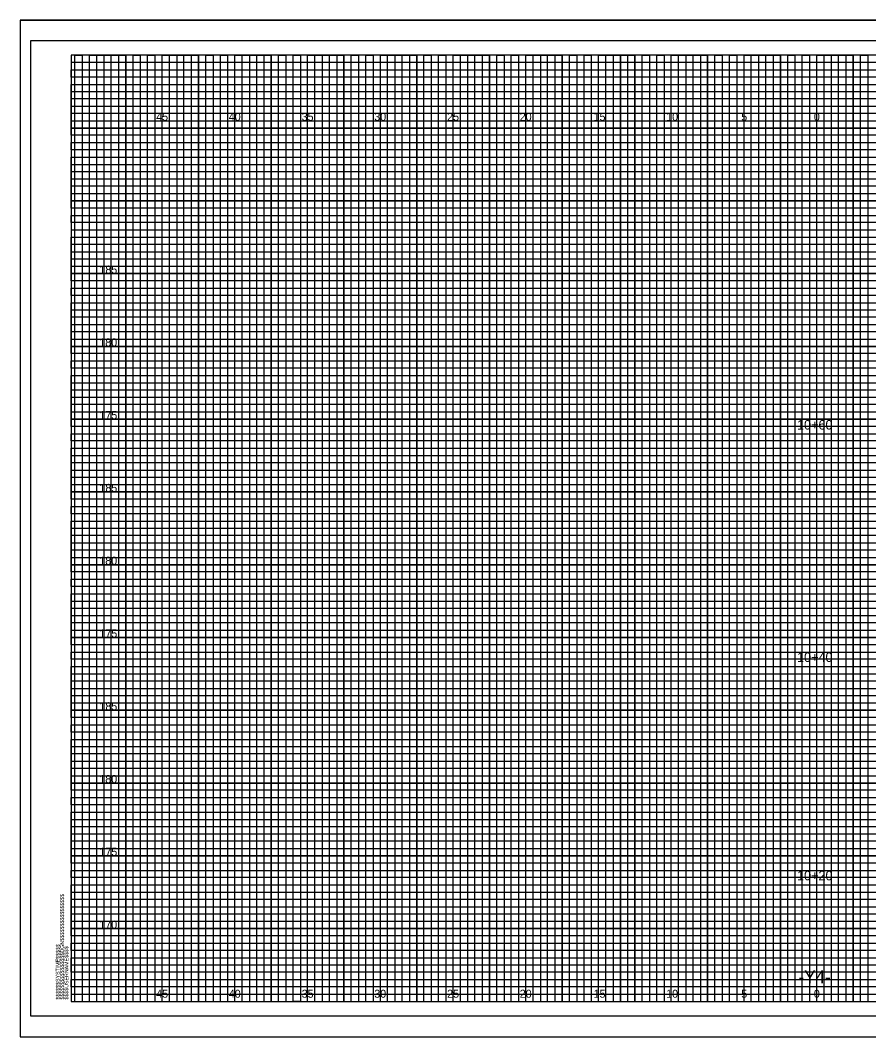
# Model space of a CAD drawing. Extents: x -4 to 103, y -2 to 138.
# Drawn here: x -3.5 to 54.8, y -2.4 to 67.4 of the extents above; entities that cross this region are included whole.
import ezdxf

# ---------------------------------------------------------------- set-up
doc = ezdxf.new("R2010")
doc.units = 0
for name, color, linetype in [('Old_Level_10', 7, 'Continuous'), ('Old_Level_3', 7, 'Continuous'), ('Old_Level_4', 7, 'Continuous'), ('Old_Level_5', 7, 'Continuous'), ('Old_Level_8', 7, 'Continuous'), ('Prop XS Dump Level', 7, 'Continuous'), ('Prop XS Elevation Labels', 7, 'Continuous'), ('Prop XS EOT Tick Mark', 7, 'Continuous'), ('Prop XS Finish Grade', 7, 'Continuous'), ('Prop XS Finish Grade Pavement', 7, 'Continuous'), ('Prop XS Subgrade Concrete', 7, 'Continuous')]:
    doc.layers.add(name, color=color, linetype=linetype)

msp = doc.modelspace()

# ---------------------------------------------------------------- linework, layer by layer
at = {"layer": 'Old_Level_10'}
for p, q in [((1.25, 0), (1.25, 65)), ((3.75, 0), (3.75, 65)), ((6.25, 0), (6.25, 65)), ((8.75, 0), (8.75, 65)), ((11.25, 0), (11.25, 65)), ((13.75, 0), (13.75, 65)), ((16.25, 0), (16.25, 65)), ((18.75, 0), (18.75, 65)), ((21.25, 0), (21.25, 65)), ((23.75, 0), (23.75, 65)), ((26.25, 0), (26.25, 65)), ((28.75, 0), (28.75, 65)), ((31.25, 0), (31.25, 65)), ((33.75, 0), (33.75, 65)), ((36.25, 0), (36.25, 65)), ((38.75, 0), (38.75, 65)), ((41.25, 0), (41.25, 65)), ((43.75, 0), (43.75, 65)), ((46.25, 0), (46.25, 65)), ((48.75, 0), (48.75, 65)), ((51.25, 0), (51.25, 65)), ((53.75, 0), (53.75, 65)), ((0, 62.5), (74.25, 62.5)), ((0, 60), (102.5, 60)), ((0, 57.5), (102.5, 57.5)), ((0, 55), (102.5, 55)), ((0, 52.5), (102.5, 52.5)), ((0, 50), (102.5, 50)), ((0, 47.5), (102.5, 47.5)), ((0, 45), (102.5, 45)), ((0, 42.5), (102.5, 42.5)), ((0, 40), (102.5, 40)), ((0, 37.5), (102.5, 37.5)), ((0, 35), (102.5, 35)), ((0, 32.5), (102.5, 32.5)), ((0, 30), (102.5, 30)), ((0, 27.5), (102.5, 27.5)), ((0, 25), (102.5, 25)), ((0, 22.5), (102.5, 22.5)), ((0, 20), (102.5, 20)), ((0, 17.5), (102.5, 17.5)), ((0, 15), (102.5, 15)), ((0, 12.5), (102.5, 12.5)), ((0, 10), (102.5, 10)), ((0, 7.5), (102.5, 7.5)), ((0, 5), (102.5, 5)), ((0, 2.5), (102.5, 2.5))]:
    msp.add_line(p, q, dxfattribs=at)
at = {"layer": 'Old_Level_3'}
for p, q in [((-3.5, 67.4), (103.4, 67.4)), ((-3.5, 67.4), (-3.5, -2.425)), ((-3.5, -2.425), (103.4, -2.425))]:
    msp.add_line(p, q, dxfattribs=at)
at = {"layer": 'Old_Level_4'}
msp.add_lwpolyline([(103, 66), (-2.8, 66), (-2.8, -1), (103, -1)], close=True, dxfattribs=at)
at = {"layer": 'Old_Level_5'}
msp.add_lwpolyline([(103.4, 67.4), (-3.5, 67.4), (-3.5, -2.425), (103.4, -2.425)], close=True, dxfattribs=at)
at = {"layer": 'Old_Level_8'}
for points in [[(1.25, 0), (1.25, 65), (3.75, 65), (3.75, 0), (6.25, 0), (6.25, 65), (8.75, 65), (8.75, 0), (11.25, 0), (11.25, 65), (13.75, 65), (13.75, 0), (16.25, 0), (16.25, 65), (18.75, 65), (18.75, 0), (21.25, 0), (21.25, 65), (23.75, 65), (23.75, 0), (26.25, 0), (26.25, 65), (28.75, 65), (28.75, 0), (31.25, 0), (31.25, 65), (33.75, 65), (33.75, 0), (36.25, 0), (36.25, 65), (38.75, 65), (38.75, 0), (41.25, 0), (41.25, 65), (43.75, 65), (43.75, 0), (46.25, 0), (46.25, 65), (48.75, 65), (48.75, 0), (51.25, 0), (51.25, 65), (53.75, 65), (53.75, 0)], [(102.5, 60), (0, 60), (0, 62.5), (74.25, 62.5)], [(102.5, 55), (0, 55), (0, 57.5), (102.5, 57.5)], [(102.5, 50), (0, 50), (0, 52.5), (102.5, 52.5)], [(102.5, 45), (0, 45), (0, 47.5), (102.5, 47.5)], [(102.5, 40), (0, 40), (0, 42.5), (102.5, 42.5)], [(102.5, 35), (0, 35), (0, 37.5), (102.5, 37.5)], [(102.5, 30), (0, 30), (0, 32.5), (102.5, 32.5)], [(102.5, 25), (0, 25), (0, 27.5), (102.5, 27.5)], [(102.5, 20), (0, 20), (0, 22.5), (102.5, 22.5)], [(102.5, 15), (0, 15), (0, 17.5), (102.5, 17.5)], [(102.5, 10), (0, 10), (0, 12.5), (102.5, 12.5)], [(102.5, 5), (0, 5), (0, 7.5), (102.5, 7.5)], [(0, 2.5), (102.5, 2.5)]]:
    msp.add_lwpolyline(points, dxfattribs=at)
at = {"layer": 'Prop XS Elevation Labels'}
msp.add_lwpolyline([(102.5, 65), (0, 65), (0, 0), (102.5, 0)], close=True, dxfattribs=at)
at = {"layer": 'Prop XS Finish Grade'}
for points in [[(0.25, 0), (0.25, 65), (0.75, 65), (0.75, 0), (1.75, 0), (1.75, 65), (2.25, 65), (2.25, 0), (2.75, 0), (2.75, 65), (3.25, 65), (3.25, 0), (4.25, 0), (4.25, 65), (4.75, 65), (4.75, 0), (5.25, 0), (5.25, 65), (5.75, 65), (5.75, 0), (6.75, 0), (6.75, 65), (7.25, 65), (7.25, 0), (7.75, 0), (7.75, 65), (8.25, 65), (8.25, 0), (9.25, 0), (9.25, 65), (9.75, 65), (9.75, 0), (10.25, 0), (10.25, 65), (10.75, 65), (10.75, 0), (11.75, 0), (11.75, 65), (12.25, 65), (12.25, 0), (12.75, 0), (12.75, 65), (13.25, 65), (13.25, 0), (14.25, 0), (14.25, 65), (14.75, 65), (14.75, 0), (15.75, 0), (15.25, 0), (15.25, 65), (15.75, 65), (15.75, 0), (16.75, 0), (16.75, 65), (17.25, 65), (17.25, 0), (17.75, 0), (17.75, 65), (18.25, 65), (18.25, 0), (19.25, 0), (19.25, 65), (19.75, 65), (19.75, 0), (20.25, 0), (20.25, 65), (20.75, 65), (20.75, 0), (21.75, 0), (21.75, 65), (22.25, 65), (22.25, 0), (22.75, 0), (22.75, 65), (23.25, 65), (23.25, 0), (24.25, 0), (24.25, 65), (24.75, 65), (24.75, 0), (25.25, 0), (25.25, 65), (25.75, 65), (25.75, 0), (26.75, 0), (26.75, 65), (27.25, 65), (27.25, 0), (27.75, 0), (27.75, 65), (28.25, 65), (28.25, 0), (29.25, 0), (29.25, 65), (29.75, 65), (29.75, 0), (30.25, 0), (30.25, 65), (30.75, 65), (30.75, 0)], [(30.75, 0), (31.75, 0), (31.75, 65), (32.25, 65), (32.25, 0), (32.75, 0), (32.75, 65), (33.25, 65), (33.25, 0), (34.25, 0), (34.25, 65), (34.75, 65), (34.75, 0), (35.25, 0), (35.25, 65), (35.75, 65), (35.75, 0), (36.75, 0), (36.75, 65), (37.25, 65), (37.25, 0), (37.75, 0), (37.75, 65), (37.75, 0)], [(38.25, 65), (38.25, 0), (39.25, 0), (39.25, 65), (39.75, 65), (39.75, 0), (40.25, 0), (40.25, 65), (40.75, 65), (40.75, 0), (41.75, 0), (41.75, 65), (42.25, 65), (42.25, 0), (42.75, 0), (42.75, 65), (43.25, 65), (43.25, 0), (43.75, 0), (44.25, 0), (44.25, 65), (44.75, 65), (44.75, 0), (45.25, 0), (45.25, 65), (45.75, 65), (45.75, 0), (46.75, 0), (46.75, 65), (47.25, 65), (47.25, 0), (47.75, 0), (47.75, 65), (48.25, 65), (48.25, 0), (49.25, 0), (49.25, 65), (49.75, 65), (49.75, 0), (50.25, 0), (50.25, 65), (50.75, 65), (50.75, 0), (51.75, 0), (51.75, 65), (52.25, 65), (52.25, 0), (52.75, 0), (52.75, 65), (53.25, 65), (53.25, 0), (54.25, 0), (54.25, 65), (54.75, 65), (54.75, 0), (55.25, 0)], [(0, 62), (0, 63), (74.25, 63), (74.25, 63.5), (0, 63.5), (0, 64), (74.25, 64), (74.25, 64.5), (0, 64.5)], [(102.5, 62), (0, 62)], [(102.5, 61), (0, 61), (0, 61.5), (102.5, 61.5)], [(102.5, 59.5), (0, 59.5), (0, 60.5), (102.5, 60.5)], [(102.5, 58.5), (0, 58.5), (0, 59), (102.5, 59)], [(102.5, 57), (0, 57), (0, 58), (102.5, 58)], [(102.5, 56), (0, 56), (0, 56.5), (102.5, 56.5)], [(102.5, 54.5), (0, 54.5), (0, 55.5), (102.5, 55.5)], [(102.5, 53.5), (0, 53.5), (0, 54), (102.5, 54)], [(0, 53), (102.5, 53)], [(102.5, 52), (0, 52)], [(102.5, 51), (0, 51), (0, 51.5), (102.5, 51.5)], [(102.5, 49.5), (0, 49.5), (0, 50.5), (102.5, 50.5)], [(102.5, 48.5), (0, 48.5), (0, 49), (102.5, 49)], [(102.5, 47), (0, 47), (0, 48), (102.5, 48)], [(102.5, 46), (0, 46), (0, 46.5), (102.5, 46.5)], [(102.5, 44.5), (0, 44.5), (0, 45.5), (102.5, 45.5)], [(102.5, 43.5), (0, 43.5), (0, 44), (102.5, 44)], [(102.5, 42), (0, 42), (0, 43), (102.5, 43)], [(102.5, 41), (0, 41), (0, 41.5), (102.5, 41.5)], [(102.5, 39.5), (0, 39.5), (0, 40.5), (102.5, 40.5)], [(102.5, 38.5), (0, 38.5), (0, 39), (102.5, 39)], [(102.5, 37), (0, 37), (0, 38), (102.5, 38)], [(102.5, 36), (0, 36), (0, 36.5), (102.5, 36.5)], [(102.5, 34.5), (0, 34.5), (0, 35.5), (102.5, 35.5)], [(102.5, 33.5), (0, 33.5), (0, 34), (102.5, 34)], [(102.5, 32), (0, 32), (0, 33), (102.5, 33)], [(102.5, 31), (0, 31), (0, 31.5)], [(0, 31.5), (102.5, 31.5)], [(102.5, 29.5), (0, 29.5), (0, 30.5), (102.5, 30.5)], [(102.5, 28.5), (0, 28.5), (0, 29), (102.5, 29)], [(102.5, 27), (0, 27), (0, 28), (102.5, 28)], [(102.5, 26), (0, 26), (0, 26.5), (102.5, 26.5)], [(102.5, 24.5), (0, 24.5), (0, 25.5), (102.5, 25.5)], [(102.5, 23.5), (0, 23.5), (0, 24), (102.5, 24)], [(102.5, 22), (0, 22), (0, 23), (102.5, 23)], [(102.5, 21), (0, 21), (0, 21.5), (102.5, 21.5)], [(102.5, 19.5), (0, 19.5), (0, 20.5), (102.5, 20.5)], [(102.5, 18.5), (0, 18.5), (0, 19), (102.5, 19)], [(102.5, 17), (0, 17), (0, 18), (102.5, 18)], [(102.5, 16), (0, 16), (0, 16.5), (102.5, 16.5)], [(102.5, 14.5), (0, 14.5), (0, 15.5), (102.5, 15.5)], [(102.5, 13.5), (0, 13.5), (0, 14), (102.5, 14)], [(102.5, 12), (0, 12), (0, 13), (102.5, 13)], [(102.5, 11), (0, 11), (0, 11.5), (102.5, 11.5)], [(102.5, 9.5), (0, 9.5), (0, 10.5), (102.5, 10.5)], [(102.5, 8.5), (0, 8.5), (0, 9), (102.5, 9)], [(102.5, 7), (0, 7), (0, 8), (102.5, 8)], [(102.5, 6), (0, 6), (0, 6.5), (102.5, 6.5)], [(102.5, 4.5), (0, 4.5), (0, 5.5), (102.5, 5.5)], [(102.5, 3.5), (0, 3.5), (0, 4), (102.5, 4)], [(102.5, 2), (0, 2), (0, 3), (102.5, 3)], [(102.5, 1), (0, 1), (0, 1.5), (102.5, 1.5)], [(0, 0.5), (102.5, 0.5)]]:
    msp.add_lwpolyline(points, dxfattribs=at)

# ---------------------------------------------------------------- texts
at = {"layer": 'Old_Level_8'}
msp.add_text('040397', height=0.0025, rotation=90, dxfattribs=at).set_placement((-0.001, 64.986))
at = {"layer": 'Prop XS Dump Level'}
for s, p in [('10+60', (49.893, 39.285)), ('10+40', (49.893, 23.319)), ('10+20', (49.893, 8.316))]:
    msp.add_text(s, height=0.65, dxfattribs=at).set_placement(p)
at = {"layer": 'Prop XS Elevation Labels'}
for s, p in [('$$$$$$$$$$$$$$$$DGN$$$$$$$$$$$$$$$$', (-0.5, 0.125)), ('$$$$$$SYSTIME$$$$$', (-0.797, 0.125)), ('$$$$USERNAME$$$$', (-0.2, 0.125))]:
    msp.add_text(s, height=0.2625, rotation=90, dxfattribs=at).set_placement(p)
at = {"layer": 'Prop XS EOT Tick Mark'}
for s, p in [('185', (1.938, 50)), ('180', (1.93, 45)), ('175', (1.938, 40)), ('185', (1.938, 35)), ('180', (1.93, 30)), ('175', (1.938, 25)), ('185', (1.938, 20)), ('180', (1.93, 15)), ('175', (1.938, 10)), ('170', (1.93, 5))]:
    msp.add_text(s, height=0.55, dxfattribs=at).set_placement(p)
at = {"layer": 'Prop XS Finish Grade Pavement'}
for s, p in [('45', (5.84, 60.5)), ('40', (10.831, 60.5)), ('35', (15.84, 60.5)), ('30', (20.831, 60.5)), ('25', (25.84, 60.5)), ('20', (30.831, 60.5)), ('15', (35.906, 60.5)), ('10', (40.897, 60.5)), ('5', (46.057, 60.5)), ('0', (51.049, 60.5)), ('0', (51.049, 60.5)), ('45', (5.84, 0.25)), ('40', (10.831, 0.25)), ('35', (15.84, 0.25)), ('30', (20.831, 0.25)), ('25', (25.84, 0.25)), ('20', (30.831, 0.25)), ('15', (35.906, 0.25)), ('10', (40.897, 0.25)), ('5', (46.057, 0.25)), ('0', (51.049, 0.25)), ('0', (51.049, 0.25))]:
    msp.add_text(s, height=0.55, dxfattribs=at).set_placement(p)
at = {"layer": 'Prop XS Subgrade Concrete'}
msp.add_text('-Y4-', height=0.875, dxfattribs=at).set_placement((49.998, 1.25))

doc.saveas('drawing.dxf')
